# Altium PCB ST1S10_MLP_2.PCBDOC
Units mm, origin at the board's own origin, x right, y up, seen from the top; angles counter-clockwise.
Board outline 152.4 x 101.6 mm, 2 copper layers (Top Layer, Bottom Layer); 15 components, 1 nets, 40 pads, 20 vias.
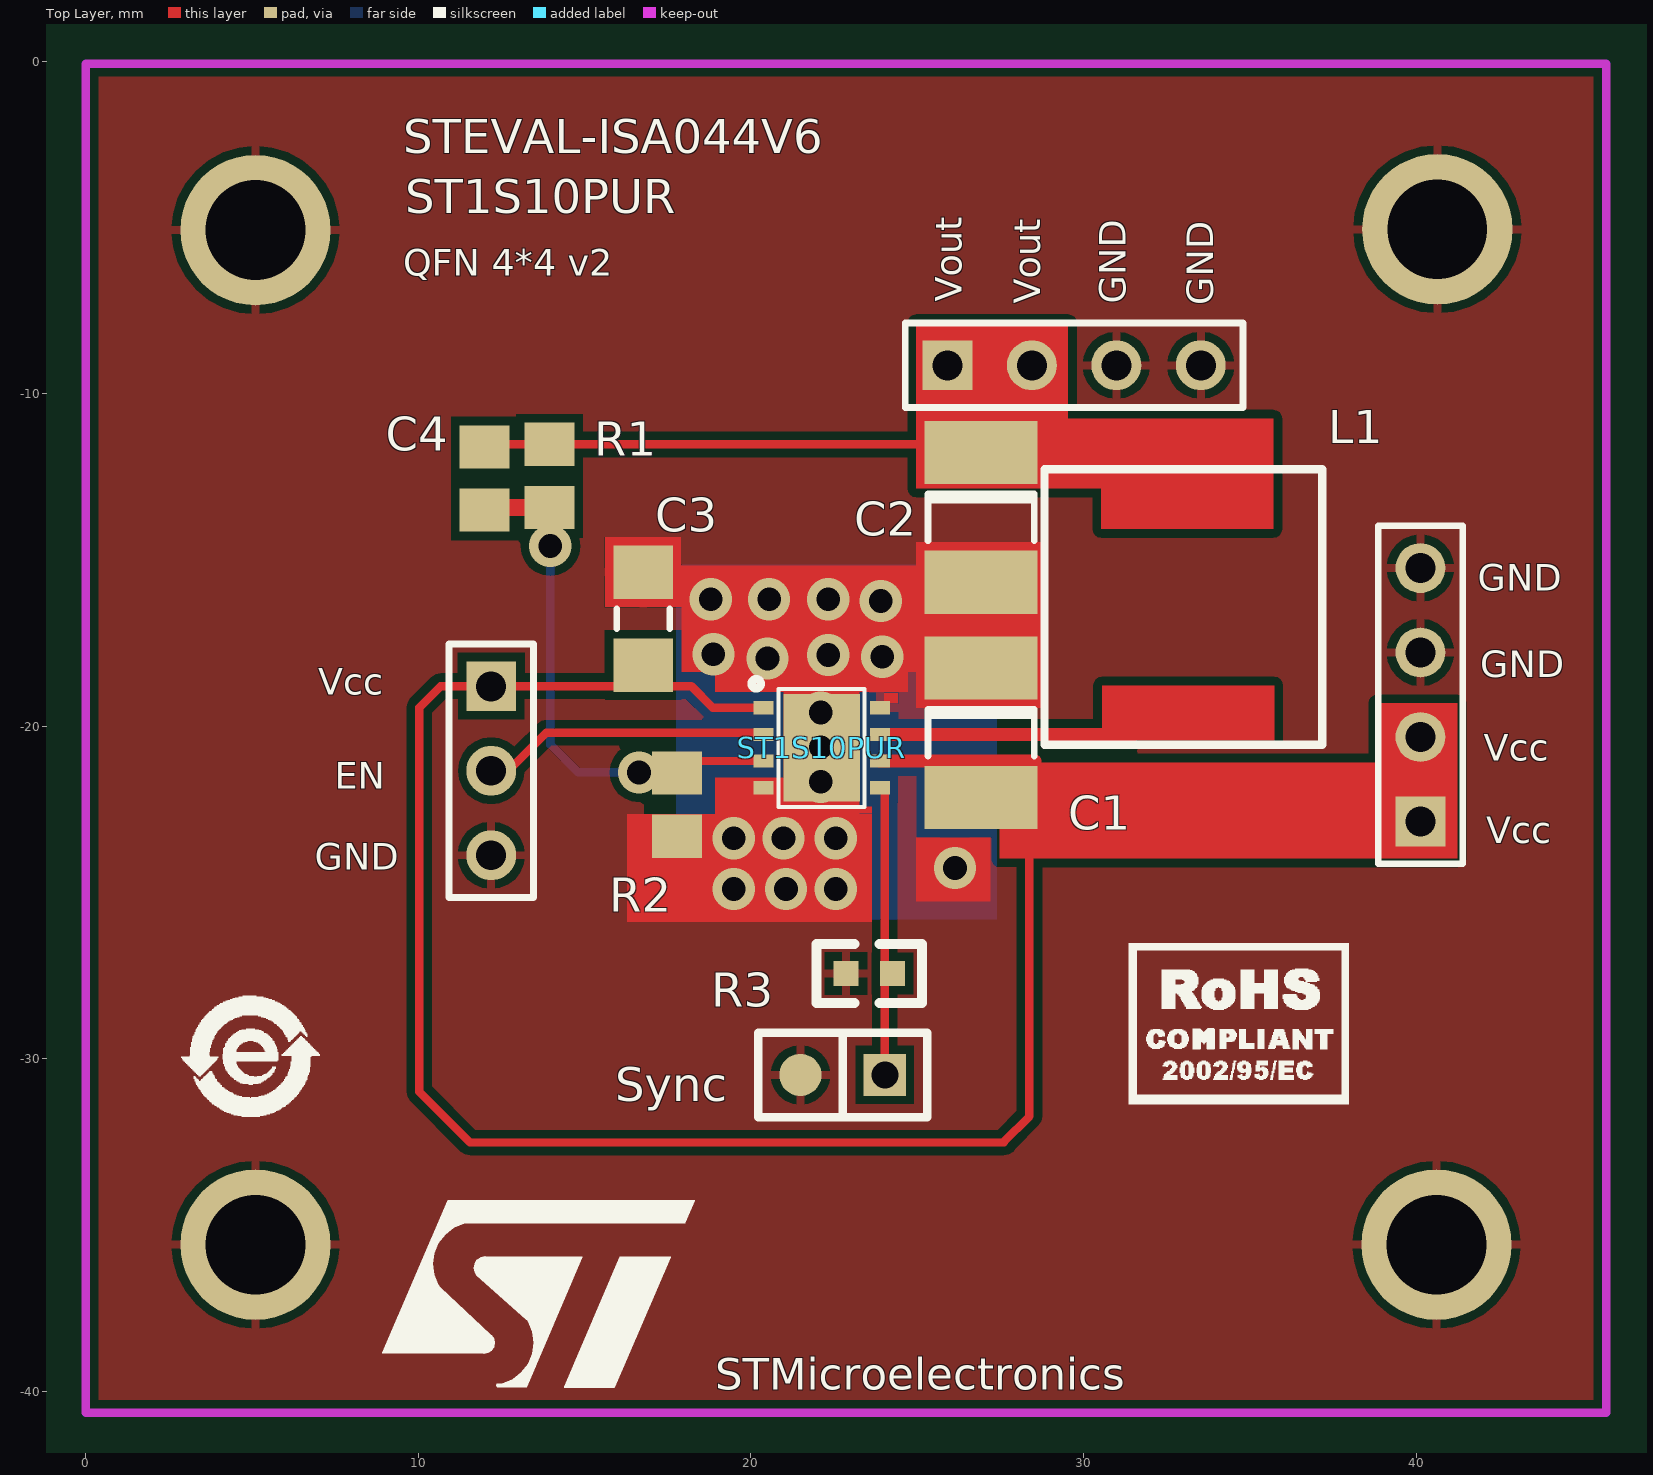
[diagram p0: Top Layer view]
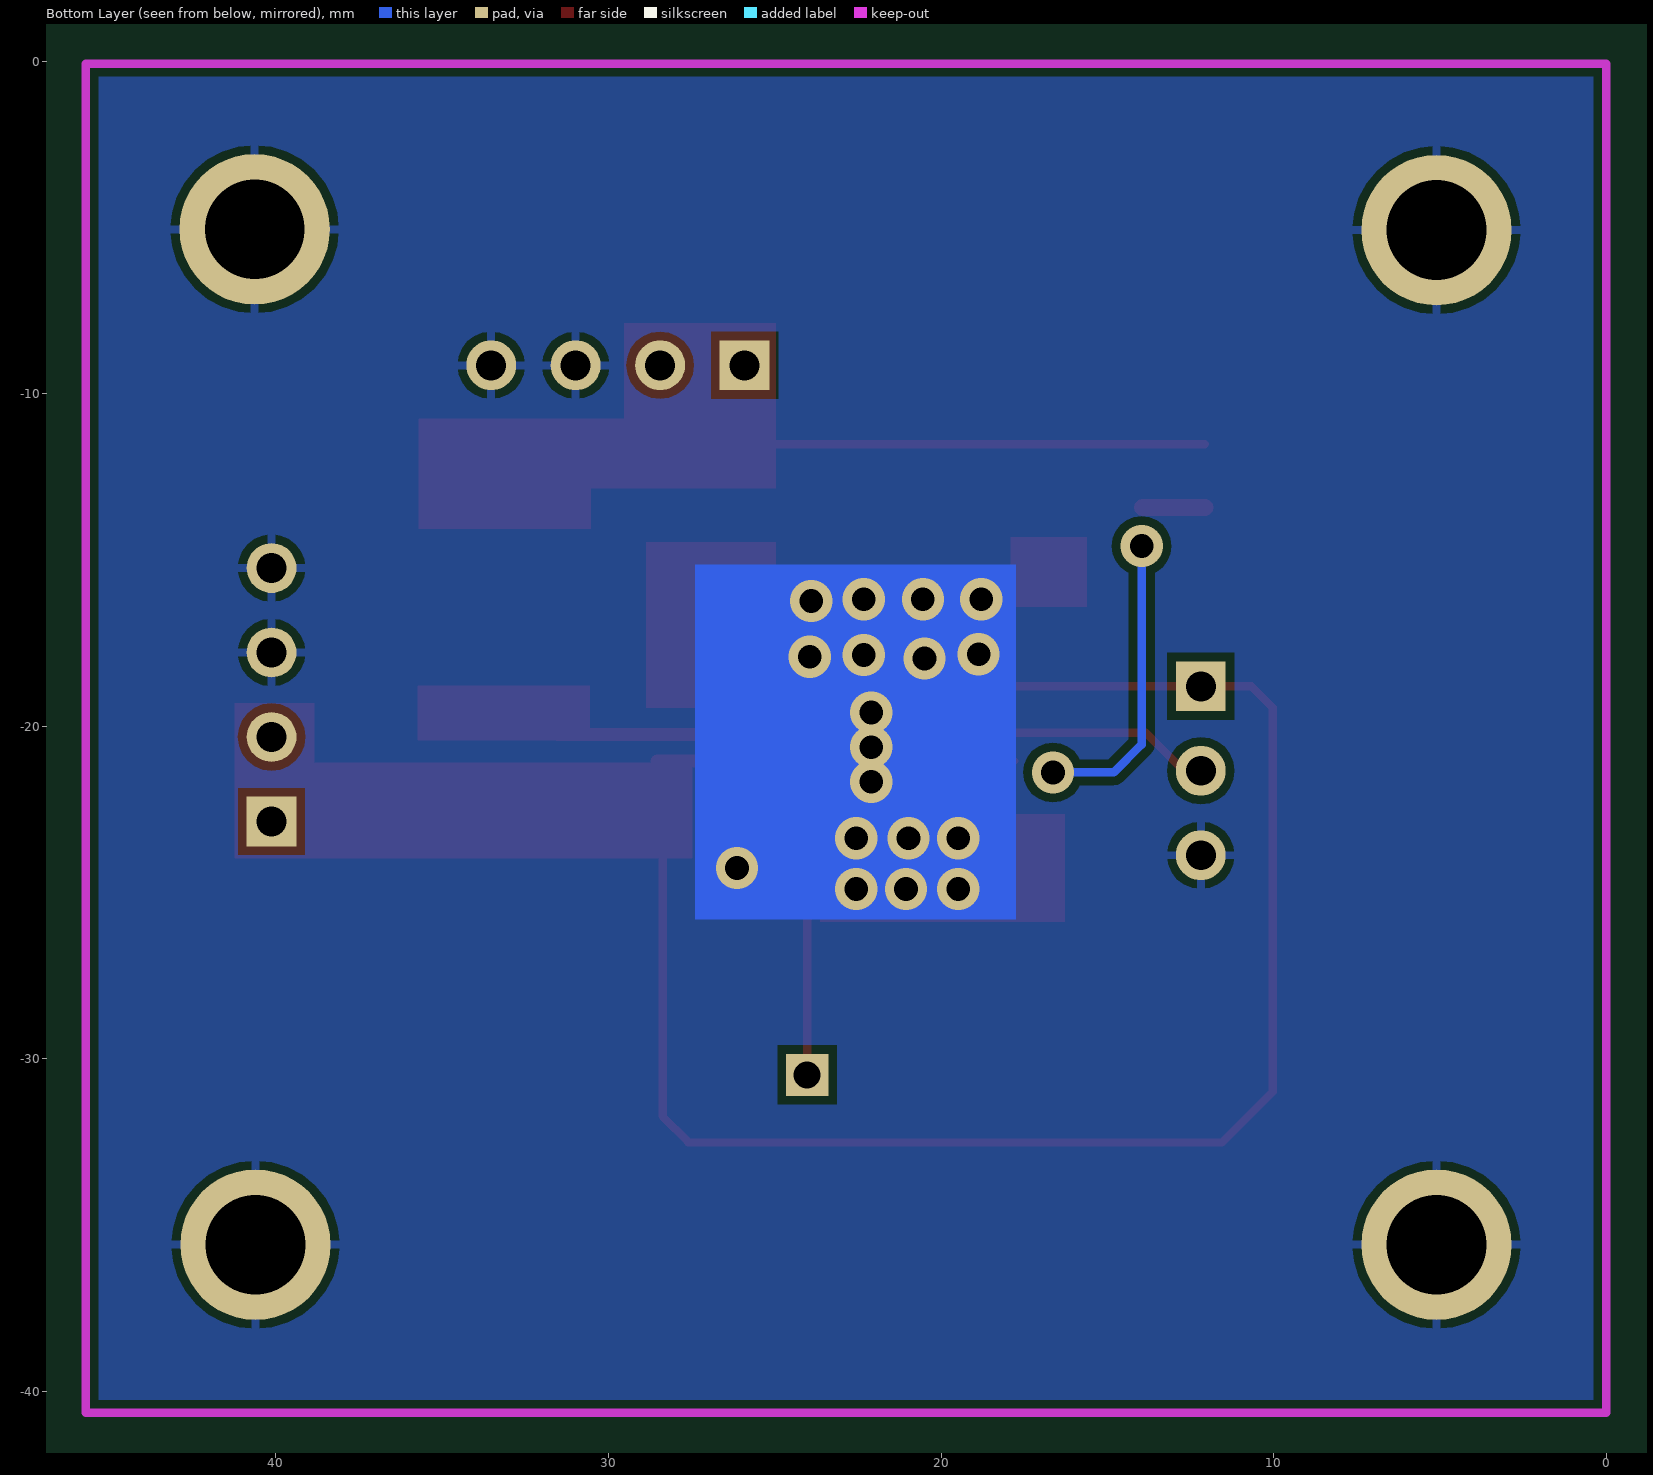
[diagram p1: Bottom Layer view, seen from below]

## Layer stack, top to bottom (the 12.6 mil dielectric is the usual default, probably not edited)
Top Layer: signal copper 0.0356
Dielectric: dielectric 0.32, FR-4, Dk 4.8
Bottom Layer: signal copper 0.0356

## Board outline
-48.26,-73.66 104.14,-73.66 104.14,27.94 -48.26,27.94

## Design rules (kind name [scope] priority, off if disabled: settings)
Clearance [All] p1: gap=0.254
ComponentClearance [All] p1: gap=0.254 collisioncheckmode=3 verticalgap=0.254
PolygonConnect [All] p1: connectstyle=Relief reliefconductorwidth=0.254 reliefentries=4 polygonreliefangle="90 Angle"
RoutingVias [All] p1: holewidth=0.711 width=1.27 viastyle="Through Hole" minholewidth=0.711 minwidth=1.27 maxholewidth=0.711 maxwidth=1.27
SolderMaskExpansion [All] p1: expansion=0.102
TestPointUsage [All] p1: valid=0 allowmultiple=FALSE
Testpoint [All] p1: side=15 testpointundercomponent=TRUE minsize=1.016 maxsize=2.54 preferedsize=1.524 minholesize=0 maxholesize=1.016 preferedholesize=0.813 testpointgrid=0.025 style=1023 order=0-112345678
Width [All] p1: maxlimit=0.254 minlimit=0.254 preferedwidth=0.254
18 further rules are at their usual default settings.

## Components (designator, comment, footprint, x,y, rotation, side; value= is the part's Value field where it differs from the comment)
C1 "4.7µF" 1812 26.924,-20.193 r270 top
C2 "22µF" 1812 26.924,-13.716 r270 top
C3 "1µF" 3216[1206] 16.764,-16.764 r270 top
C4 "4700pF*" 2012[0805] 11.989,-12.548 r90 top
R1 "56K" 2012[0805] 13.945,-12.471 r90 top
R2 "18K" 2012[0805] 17.78,-22.352 r90 top
R3 "10K" 0603 22.86,-27.432 r0 top
ST1S10PUR "ST1S10PUR" "VFDFPN 8L 4X4 0,8 ST1S10" 23.876,-21.844 r90 top
Sync "" SIP2 24.028,-30.48 r180 top
? "" CH_ROHS 5.08,-29.972 r0 top
? "" HDR1X3 12.192,-18.796 r270 top
? "" HDR1X4 25.908,-9.144 r0 top
? "" HDR1X4 40.132,-22.86 r90 top
? "" LOGOUFFICIALE_MEDIUM 9.144,-39.624 r0 top
? "Comment" EU_ROHS_1 34.544,-29.464 r0 top

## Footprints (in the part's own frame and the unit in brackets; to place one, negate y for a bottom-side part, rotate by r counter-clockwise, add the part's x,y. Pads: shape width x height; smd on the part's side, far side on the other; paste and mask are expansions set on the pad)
0603 [mil]
  rect 30x30 smd: 1(0,0) 2(55,0)
  silkscreen extent -35,-35 90,35
1812 [mm] "Chip Capacitor; Body 4.5 x 3.2 mm (LxW typ)"
  rect 1.9x3.4 smd: 1(-1.95,0) 2(1.95,0)
  silkscreen extent -0.7,-1.6 0.7,1.6
2012[0805] [mm] "Chip Resistor; Body 2.0 x 1.3 mm (LxW typ)"
  rect 1.3x1.5 smd: 1(-0.95,0) 2(0.95,0)
3216[1206] [mm] "Chip Resistor; Body 3.2 x 1.6 mm (LxW typ)"
  rect 1.6x1.8 smd: 1(-1.4,0) 2(1.4,0)
  silkscreen extent -0.3,-0.8 0.3,0.8
CH_ROHS [mm]
  silkscreen extent -2.21,-1.75 1.96,1.85
EU_ROHS_1 [mm]
  silkscreen extent -3.17,-1.88 3.43,2.92
HDR1X3 [mm] "Connector; Header; 3 Position"
  rect 1.5x1.5 hole 0.9: 1(0,0)
  round 1.5 hole 0.9: 2(2.54,0) 3(5.08,0)
  silkscreen extent -1.27,-1.27 6.35,1.27
HDR1X4 [mm] "Connector; Header; 4 Position"
  rect 1.5x1.5 hole 0.9: 1(0,0)
  round 1.5 hole 0.9: 2(2.54,0) 3(5.08,0) 4(7.62,0)
  silkscreen extent -1.27,-1.27 8.89,1.27
LOGOUFFICIALE_MEDIUM [mm]
  silkscreen extent -0.23,-0.26 9.17,5.38
SIP2 [mil]
  rect 50x50 hole 32: 1(0,0)
  round 50 smd: 2(100,0)
  silkscreen extent -50,-50 150,50
"VFDFPN 8L 4X4 0,8 ST1S10" [mil]
  rect 15.73x23.6 smd: 1(0,0) 2(31.5,0) 3(63,0) 4(94.5,0) 5(94.5,137.8) 6(63,137.8) 7(31.5,137.8) 8(0,137.8)
  rect 127.57x90.53 smd: 9(47.25,68.9)

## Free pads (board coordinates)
  round 4.524 hole 3: 0(5.105,-5.08) 1(5.105,-35.585) 2(40.615,-35.585) 3(40.64,-5.055)

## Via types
v1: diameter 1.27, hole 0.711, Top Layer to Bottom Layer, 20 vias

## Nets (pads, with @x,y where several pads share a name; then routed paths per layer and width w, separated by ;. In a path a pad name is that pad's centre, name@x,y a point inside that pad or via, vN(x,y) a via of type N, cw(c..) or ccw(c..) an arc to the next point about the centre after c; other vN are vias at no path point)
GND: ?.3 ?.4 C1.1 C2.2 C3.1 pad.0 pad.1 pad.2 pad.3 R2.1 R3.1 ST1S10PUR.4 ST1S10PUR.8 ST1S10PUR.9 Sync.2
  other v1: 19.482,-24.892 21.057,-24.892 22.555,-24.892 26.137,-24.257 20.98,-23.368 22.098,-21.666 22.098,-20.625 22.098,-19.583
pads on no net: ?.1 ?.2 C1.2 C2.1 C3.2 C4.1 C4.2 R1.1 R1.2 R2.2 R3.2 ST1S10PUR.1 ST1S10PUR.2 ST1S10PUR.3 ST1S10PUR.5 ST1S10PUR.6 ST1S10PUR.7 Sync.1
copper on no net: | length 108.8
  Top Layer w0.25: 12.065,-11.521 26.873,-11.521 ; 12.7,-21.336 13.843,-20.193 20.376,-20.193 ; 17.805,-21.044 20.376,-21.044 ; 18.212,-18.796 12.192,-18.796 10.668,-18.796 10.033,-19.431 10.033,-30.988 11.557,-32.512 27.61,-32.512 ; 27.597,-32.499 28.372,-31.725 28.372,-23.012
  Top Layer w0.254: 18.212,-18.796 18.86,-19.444 20.376,-19.444 ; 24.028,-30.48 24.028,-21.844 ; 27.61,-32.512 27.61,-32.487 ; 12.192,-21.336 12.7,-21.336 12.192,-21.336
  Top Layer w0.4: 23.876,-21.044 28.537,-21.044 ; 23.876,-20.244 31.547,-20.244
  Top Layer w0.5: 12.065,-13.421 13.945,-13.421
  Bottom Layer w0.254: v1(13.97,-14.58) 13.97,-20.549 14.808,-21.387 v1(16.637,-21.387)
  other v1: 19.482,-23.368 22.555,-23.368 20.498,-17.958 23.952,-17.907 22.327,-17.856 18.872,-17.831 23.901,-16.231 18.796,-16.18 20.549,-16.18 22.327,-16.18

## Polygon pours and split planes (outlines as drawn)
GND on Top Layer "Top Layer" (solid): 0,-0.076 45.72,-0.076 45.72,-40.64 0,-40.64
GND on Bottom Layer "Top Layer" (solid): 0,-0.076 45.72,-0.076 45.72,-40.64 0,-40.64

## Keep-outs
Keep-Out Layer:
  lines w0.254: 0,-40.64 45.72,-40.64 45.72,-0.076 0,-0.076 0,-40.64

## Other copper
Top Layer:
  rectangle net GND: 15.61,-16.418 17.918,-14.31
  rectangle net GND: 24.97,-25.273 27.203,-23.347
  rectangle net GND: 18.923,-22.657 21.285,-21.539
  rectangle net GND: 23.266,-22.608 23.64,-22.403
  rectangle net GND: 20.98,-22.809 23.266,-18.542
  rectangle net GND: 16.281,-25.883 23.64,-22.631
  rectangle net GND: 24.003,-19.317 24.43,-18.99
  rectangle net GND: 18.923,-18.974 24.717,-18.37
  rectangle net GND: 24.97,-15.793 28.878,-14.462
  rectangle net GND: 24.97,-19.447 28.878,-18.37
  rectangle net GND: 17.918,-18.37 28.878,-15.164
  region: 35.712,-12.852 35.712,-10.744 24.968,-10.744 24.968,-12.852
  rectangle: 30.531,-14.072 35.712,-12.421
  rectangle: 30.556,-20.422 35.738,-18.771
  rectangle: 27.483,-23.978 41.25,-21.082
  rectangle: 38.837,-21.184 41.25,-19.304
  rectangle: 24.968,-11.532 29.54,-7.874
Bottom Layer:
  rectangle net GND: 17.755,-25.806 27.407,-15.138

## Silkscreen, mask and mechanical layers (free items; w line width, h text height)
Top Overlay:
  circle w0.254: c20.158,-18.72 r0.137
  lines w0.125: 20.828,-22.428 23.419,-22.428 23.419,-18.872 20.828,-18.872 20.828,-22.428
  lines w0.254: 28.829,-20.549 37.186,-20.549 37.186,-12.268 28.829,-12.268 28.829,-20.549
  text "STEVAL-ISA044V6" at 9.55,-2.769 h1.02
  text "ST1S10PUR" at 9.601,-4.572 h1.02
  text "QFN 4*4 v2" at 9.55,-6.452 h0.8
  text "Vout" at 26.34,-7.239 h0.8 r90
  text "Vout" at 28.702,-7.29 h0.8 r90
  text "GND" at 31.267,-7.29 h0.8 r90
  text "GND" at 33.909,-7.341 h0.8 r90
  text "L1" at 37.363,-11.481 h1
  text "GND" at 41.859,-15.926 h0.8
  text "GND" at 41.935,-18.517 h0.8
  text "Vcc" at 6.985,-19.05 h0.8
  text "Vcc" at 42.037,-21.031 h0.8
  text "EN" at 7.493,-21.869 h0.8
  text "Vcc" at 42.113,-23.52 h0.8
  text "GND" at 6.883,-24.308 h0.8
Top Solder:
  rectangle: 30.886,-13.97 35.331,-12.471
  rectangle: 30.886,-20.345 35.331,-18.847
  text "VG" at 39.395,-26.619 h1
